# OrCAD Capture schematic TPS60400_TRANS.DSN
size D; title: TPS60400: Unregulated, 60mA, Charge Pump Voltage Inverter; rev: 1.0; note: Datasheet: <SLVS324C>     EVM: <SLVU051>; note: Synchronous Step Down Converter
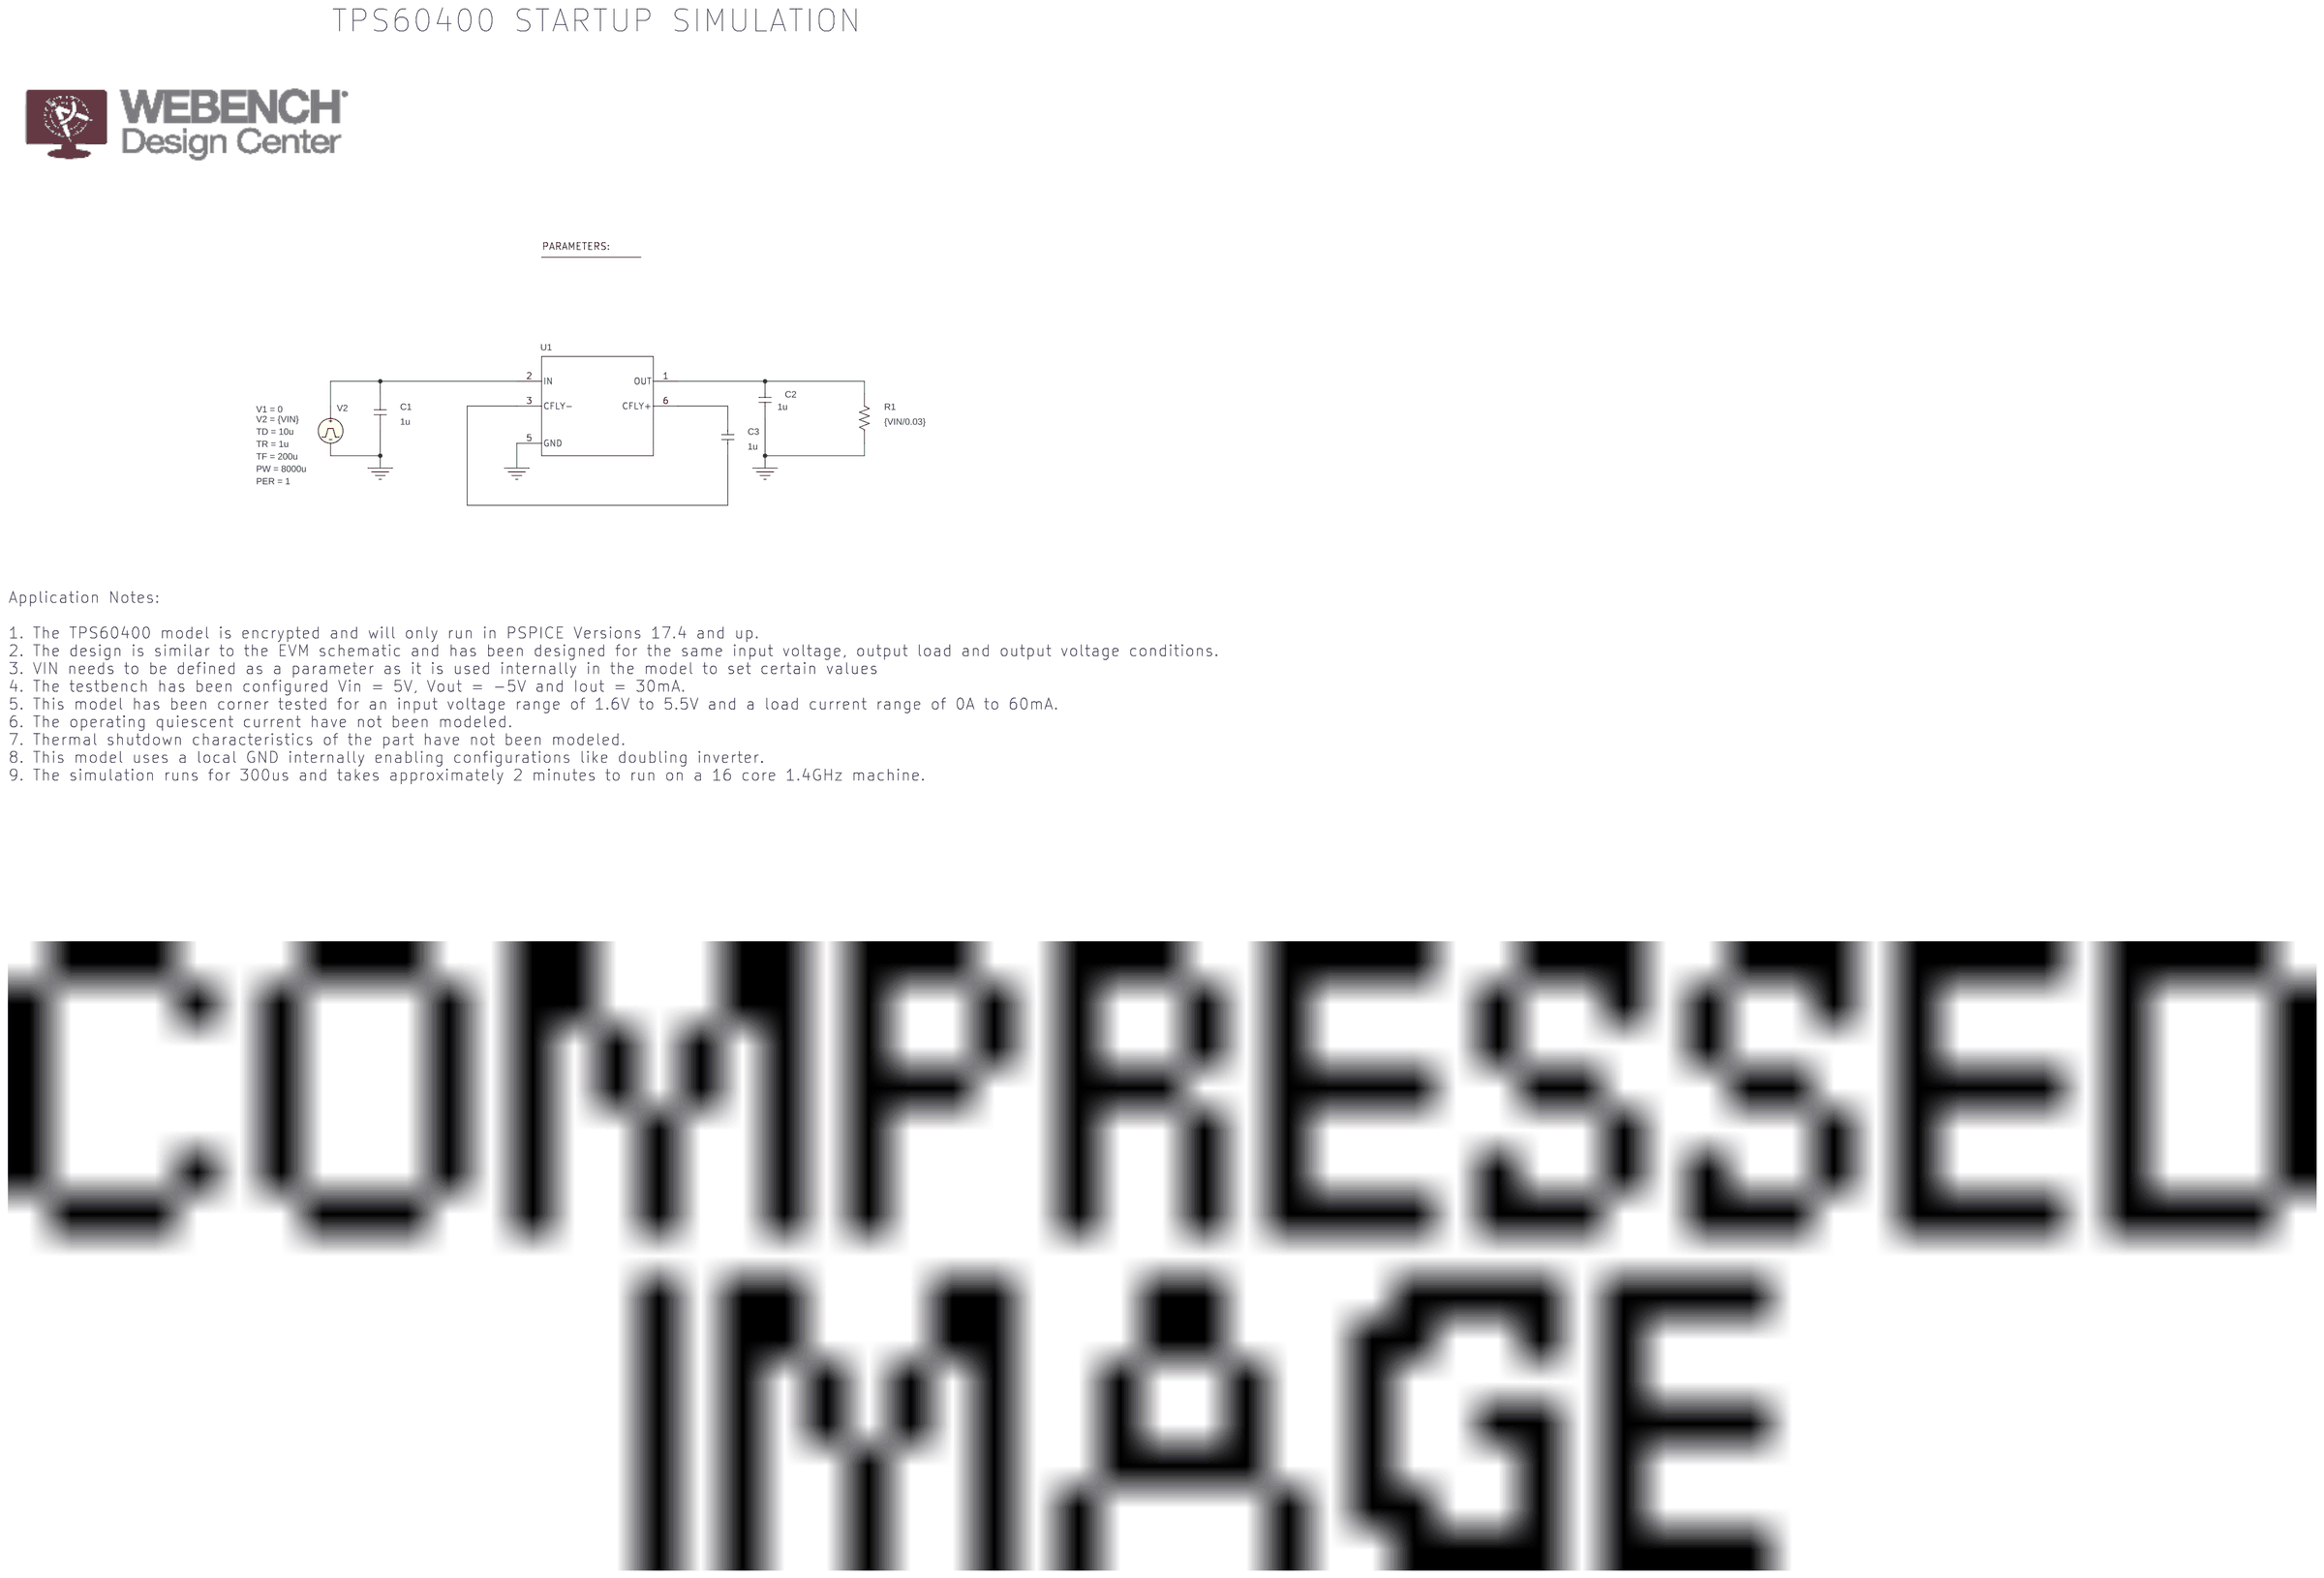
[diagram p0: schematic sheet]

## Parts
1  PARAM
C1  1u  [cap196]
C2  1u  [cap196]
C3  1u  [cap196]
R1  {VIN/0.03}  [AXRC05]
U1  Value  [DRL0006A-MFG]
V2  VPULSE

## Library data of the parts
1 = PARAM: VIN: 5
C1 C2 = C
C3 = C: IC: 0
R1 = R
U1 = TPS60400_TRANS
V2 = VPULSE: PER: 1; PW: 8000u; TD: 10u; TF: 200u; TR: 1u; V1: 0; V2: {VIN}

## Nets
0: C1.1 C2.1 R1.1 U1.5(GND) V2.2(-)
N16769383: C1.2 U1.2(IN) V2.1(+)
N16770077: C2.2 R1.2 U1.1(OUT)
N16771502: C3.1 U1.3(CFLY-)
N16772529: C3.2 U1.6(CFLY+)

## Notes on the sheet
- TPS60400 STARTUP SIMULATION
- Application Notes:
  1. The TPS60400 model is encrypted and will only run in PSPICE Versions 17.4 and up.
  2. The design is similar to the EVM schematic and has been designed for the same input voltage, output load and output voltage conditions.
  3. VIN needs to be defined as a parameter as it is used internally in the model to set certain values
  4. The testbench has been configured Vin = 5V, Vout = -5V and Iout = 30mA.
  5. This model has been corner tested for an input voltage range of 1.6V to 5.5V and a load current range of 0A to 60mA.
  6. The operating quiescent current have not been modeled.
  7. Thermal shutdown characteristics of the part have not been modeled.
  8. This model uses a local GND internally enabling configurations like doubling inverter.
  9. The simulation runs for 300us and takes approximately 2 minutes to run on a 16 core 1.4GHz machine.
